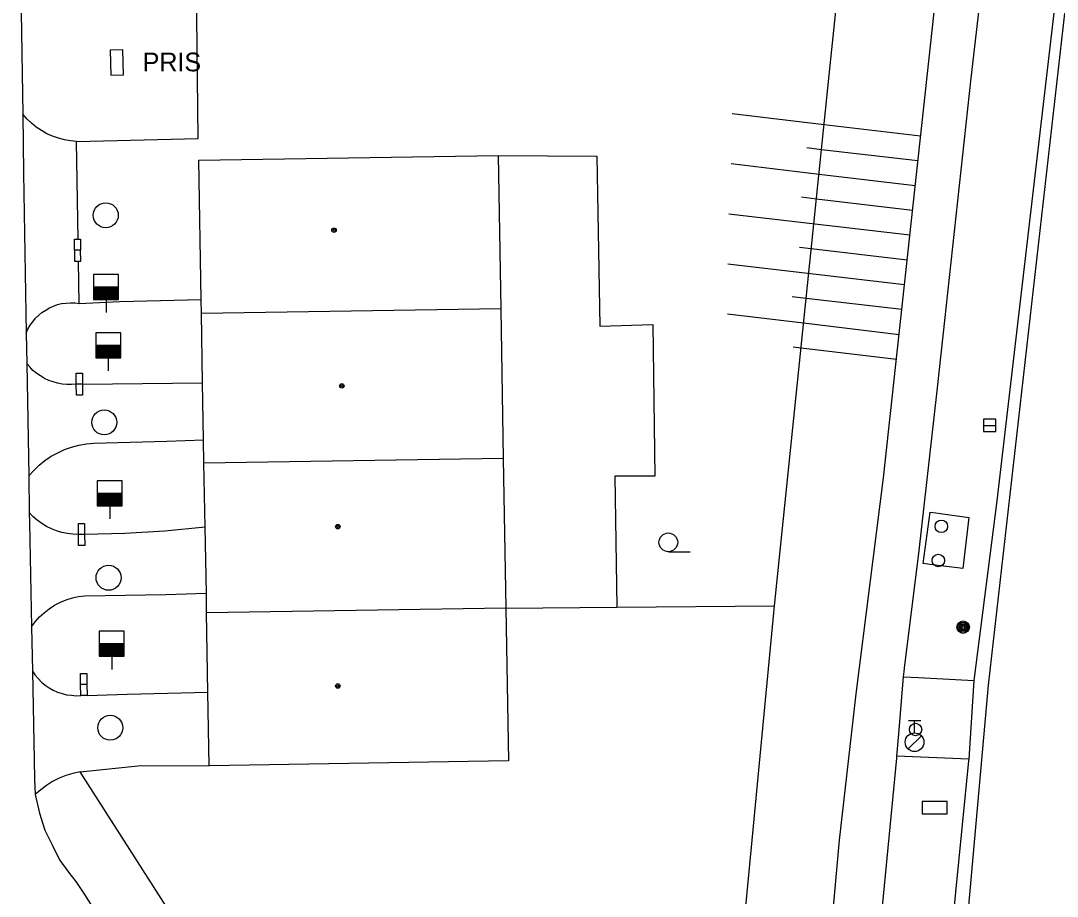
# Model space of a CAD drawing. Extents: x -595546 to -593986, y -1160845 to -1159202.
# Drawn here: x -594714.12 to -594672.57, y -1160187.36 to -1160152.26 of the extents above; entities that cross this region are included whole.
import ezdxf

# ---------------------------------------------------------------- set-up
doc = ezdxf.new("R2010")
doc.units = 0
for name, color, linetype in [('Level 24', 7, 'Continuous'), ('Level 25', 7, 'Continuous'), ('Level 27', 7, 'Continuous'), ('Level 28', 7, 'Continuous'), ('Level 36', 7, 'Continuous'), ('Level 39', 7, 'Continuous'), ('plynovod - povrch.  znaky - PRIS skut. velikost', 7, 'Continuous'), ('silnoproud - povrch.  znaky a  RIS  skut. velikost', 7, 'Continuous'), ('Specificka linie pasportu komunikaci', 7, 'Continuous'), ('TM - budovy zdene_ betonove - VP', 7, 'Continuous'), ('TM - chodniky - VP', 7, 'Continuous'), ('TM - komunikace - VP', 7, 'Continuous'), ('TM - letecke snimky - pomocna linie', 7, 'Continuous'), ('TM - popis objektu', 7, 'Continuous'), ('TM - rozhrani ploch obecne - VP', 7, 'Continuous'), ('TM - srafovani', 7, 'Continuous')]:
    doc.layers.add(name, color=color, linetype=linetype)

msp = doc.modelspace()

# ---------------------------------------------------------------- linework, layer by layer
at = {"layer": 'Level 24'}
for points in [[(-594710.533, -1160153.447), (-594710.507, -1160154.446), (-594710.007, -1160154.433), (-594710.033, -1160153.434)], [(-594677.987, -1160184.058), (-594676.987, -1160184.058), (-594676.987, -1160183.558), (-594677.987, -1160183.558)]]:
    msp.add_lwpolyline(points, close=True, dxfattribs=at)
at = {"layer": 'Level 25'}
for radius in [0.25, 0.2, 0.15, 0.1, 0.05]:
    msp.add_circle((-594676.34, -1160176.57), radius, dxfattribs=at)
at = {"layer": 'Level 27'}
msp.add_line((-594675.53, -1160168.48), (-594675.03, -1160168.48), dxfattribs=at)
msp.add_lwpolyline([(-594675.53, -1160168.73), (-594675.03, -1160168.73), (-594675.03, -1160168.23), (-594675.53, -1160168.23)], close=True, dxfattribs=at)
for centre in [(-594710.71, -1160160.06), (-594710.77, -1160168.36), (-594710.6, -1160174.59), (-594710.53, -1160180.6)]:
    msp.add_circle(centre, 0.5, dxfattribs=at)
at = {"layer": 'Level 28'}
for p, q in [((-594711.2, -1160162.93), (-594710.2, -1160162.93)), ((-594711.2, -1160162.98), (-594710.2, -1160162.98)), ((-594711.2, -1160163.03), (-594710.2, -1160163.03)), ((-594711.2, -1160163.08), (-594710.2, -1160163.08)), ((-594711.2, -1160163.13), (-594710.2, -1160163.13)), ((-594711.2, -1160163.18), (-594710.2, -1160163.18)), ((-594711.2, -1160163.23), (-594710.2, -1160163.23)), ((-594711.2, -1160163.28), (-594710.2, -1160163.28)), ((-594711.2, -1160163.33), (-594710.2, -1160163.33)), ((-594711.2, -1160163.38), (-594710.2, -1160163.38)), ((-594710.7, -1160163.43), (-594710.7, -1160163.96)), ((-594711.11, -1160165.27), (-594710.11, -1160165.27)), ((-594711.11, -1160165.32), (-594710.11, -1160165.32)), ((-594711.11, -1160165.37), (-594710.11, -1160165.37)), ((-594711.11, -1160165.42), (-594710.11, -1160165.42)), ((-594711.11, -1160165.47), (-594710.11, -1160165.47)), ((-594711.11, -1160165.52), (-594710.11, -1160165.52)), ((-594711.11, -1160165.57), (-594710.11, -1160165.57)), ((-594711.11, -1160165.62), (-594710.11, -1160165.62)), ((-594711.11, -1160165.67), (-594710.11, -1160165.67)), ((-594711.11, -1160165.72), (-594710.11, -1160165.72)), ((-594710.61, -1160165.77), (-594710.61, -1160166.3)), ((-594711.05, -1160171.2), (-594710.05, -1160171.2)), ((-594711.05, -1160171.25), (-594710.05, -1160171.25)), ((-594711.05, -1160171.3), (-594710.05, -1160171.3)), ((-594711.05, -1160171.35), (-594710.05, -1160171.35)), ((-594711.05, -1160171.4), (-594710.05, -1160171.4)), ((-594711.05, -1160171.45), (-594710.05, -1160171.45)), ((-594711.05, -1160171.5), (-594710.05, -1160171.5)), ((-594711.05, -1160171.55), (-594710.05, -1160171.55)), ((-594711.05, -1160171.6), (-594710.05, -1160171.6)), ((-594711.05, -1160171.65), (-594710.05, -1160171.65)), ((-594710.55, -1160171.7), (-594710.55, -1160172.23)), ((-594710.97, -1160177.23), (-594709.97, -1160177.23)), ((-594710.97, -1160177.28), (-594709.97, -1160177.28)), ((-594710.97, -1160177.33), (-594709.97, -1160177.33)), ((-594710.97, -1160177.38), (-594709.97, -1160177.38)), ((-594710.97, -1160177.43), (-594709.97, -1160177.43)), ((-594710.97, -1160177.48), (-594709.97, -1160177.48)), ((-594710.97, -1160177.53), (-594709.97, -1160177.53)), ((-594710.97, -1160177.58), (-594709.97, -1160177.58)), ((-594710.97, -1160177.63), (-594709.97, -1160177.63)), ((-594710.97, -1160177.68), (-594709.97, -1160177.68)), ((-594710.47, -1160177.73), (-594710.47, -1160178.26)), ((-594678.54, -1160180.305), (-594678.04, -1160180.305)), ((-594678.29, -1160180.805), (-594678.29, -1160180.305)), ((-594678.548, -1160181.452), (-594678.018, -1160180.922))]:
    msp.add_line(p, q, dxfattribs=at)
for points in [[(-594711.2, -1160163.43), (-594710.2, -1160163.43), (-594710.2, -1160162.43), (-594711.2, -1160162.43)], [(-594711.11, -1160165.77), (-594710.11, -1160165.77), (-594710.11, -1160164.77), (-594711.11, -1160164.77)], [(-594711.05, -1160171.7), (-594710.05, -1160171.7), (-594710.05, -1160170.7), (-594711.05, -1160170.7)], [(-594710.97, -1160177.73), (-594709.97, -1160177.73), (-594709.97, -1160176.73), (-594710.97, -1160176.73)]]:
    msp.add_lwpolyline(points, close=True, dxfattribs=at)
for centre, radius in [((-594677.22, -1160172.53), 0.25), ((-594677.34, -1160173.9), 0.25), ((-594678.25, -1160180.67), 0.25), ((-594678.29, -1160181.18), 0.375)]:
    msp.add_circle(centre, radius, dxfattribs=at)
at = {"layer": 'Level 36'}
msp.add_line((-594688.16, -1160173.545), (-594687.285, -1160173.545), dxfattribs=at)
msp.add_circle((-594688.16, -1160173.17), 0.375, dxfattribs=at)
at = {"layer": 'Level 39'}
for centre, radius in [((-594701.56, -1160160.66), 0.09), ((-594701.56, -1160160.66), 0.0398), ((-594701.25, -1160166.9), 0.09), ((-594701.25, -1160166.9), 0.0398), ((-594701.41, -1160172.54), 0.09), ((-594701.41, -1160172.54), 0.0398), ((-594701.41, -1160178.93), 0.09), ((-594701.41, -1160178.93), 0.0398)]:
    msp.add_circle(centre, radius, dxfattribs=at)
at = {"layer": 'plynovod - povrch.  znaky - PRIS skut. velikost'}
for points in [[(-594711.97, -1160161.02), (-594711.82, -1160161.02)], [(-594711.97, -1160161.46), (-594711.97, -1160161.02)], [(-594711.82, -1160161.02), (-594711.72, -1160161.02), (-594711.72, -1160161.46)], [(-594711.72, -1160161.46), (-594711.81, -1160161.46), (-594711.97, -1160161.46)], [(-594711.9, -1160166.39), (-594711.65, -1160166.39), (-594711.65, -1160166.83)], [(-594711.9, -1160166.83), (-594711.9, -1160166.39)], [(-594711.65, -1160166.83), (-594711.9, -1160166.83)], [(-594711.81, -1160172.41), (-594711.56, -1160172.41), (-594711.56, -1160172.85)], [(-594711.81, -1160172.85), (-594711.81, -1160172.41)], [(-594711.56, -1160172.85), (-594711.81, -1160172.85)], [(-594711.72, -1160178.87), (-594711.72, -1160178.43), (-594711.47, -1160178.43), (-594711.47, -1160178.87)], [(-594711.47, -1160178.87), (-594711.72, -1160178.87)]]:
    msp.add_lwpolyline(points, dxfattribs=at)
at = {"layer": 'silnoproud - povrch.  znaky a  RIS  skut. velikost'}
for points in [[(-594711.97, -1160161.46), (-594711.96, -1160161.9), (-594711.8, -1160161.9)], [(-594711.8, -1160161.9), (-594711.71, -1160161.9), (-594711.72, -1160161.46)], [(-594711.65, -1160166.83), (-594711.64, -1160167.27), (-594711.89, -1160167.27), (-594711.9, -1160166.83)], [(-594711.56, -1160172.85), (-594711.55, -1160173.29), (-594711.8, -1160173.29), (-594711.81, -1160172.85)], [(-594711.71, -1160179.31), (-594711.72, -1160178.87)], [(-594711.47, -1160178.87), (-594711.46, -1160179.31)], [(-594711.46, -1160179.31), (-594711.71, -1160179.31)]]:
    msp.add_lwpolyline(points, dxfattribs=at)
at = {"layer": 'Specificka linie pasportu komunikaci'}
for points in [[(-594670.43, -1160132.17), (-594672.44, -1160149.65), (-594674.99, -1160171.51), (-594675.92, -1160178.71)], [(-594678.73, -1160178.56), (-594678.13, -1160178.59), (-594675.92, -1160178.71)], [(-594675.92, -1160178.71), (-594676.12, -1160181.86)], [(-594676.12, -1160181.86), (-594679, -1160181.74)], [(-594676.12, -1160181.86), (-594676.13, -1160181.93), (-594677.42, -1160195.02), (-594677.85, -1160199.94)]]:
    msp.add_lwpolyline(points, dxfattribs=at)
at = {"layer": 'TM - budovy zdene_ betonove - VP'}
for points in [[(-594706.98, -1160157.85), (-594694.98, -1160157.66)], [(-594706.89, -1160163.43), (-594706.98, -1160157.85)], [(-594694.98, -1160157.66), (-594694.88, -1160163.81)], [(-594706.88, -1160164), (-594706.89, -1160163.43)], [(-594694.88, -1160163.81), (-594706.88, -1160164)], [(-594706.83, -1160166.77), (-594706.88, -1160164)], [(-594694.88, -1160163.81), (-594694.78, -1160169.81)], [(-594706.8, -1160169.06), (-594706.83, -1160166.77)], [(-594706.78, -1160170), (-594706.8, -1160169.06)], [(-594694.78, -1160169.81), (-594706.78, -1160170)], [(-594694.78, -1160169.81), (-594694.68, -1160175.81)], [(-594706.73, -1160172.56), (-594706.78, -1160170)], [(-594706.68, -1160175.2), (-594706.73, -1160172.56)], [(-594706.67, -1160175.99), (-594706.68, -1160175.2)], [(-594694.68, -1160175.81), (-594706.67, -1160175.99)], [(-594706.62, -1160179.17), (-594706.67, -1160175.99)], [(-594694.68, -1160175.81), (-594694.57, -1160181.93)], [(-594706.57, -1160182.13), (-594706.62, -1160179.17)], [(-594694.57, -1160181.93), (-594706.57, -1160182.13)]]:
    msp.add_lwpolyline(points, dxfattribs=at)
at = {"layer": 'TM - chodniky - VP'}
msp.add_lwpolyline([(-594679.54, -1160170.59), (-594674.28, -1160122.31), (-594671.81, -1160100.61)], dxfattribs=at)
at = {"layer": 'TM - komunikace - VP'}
for points in [[(-594678.62, -1160214.43), (-594678.31, -1160212.31), (-594675.32, -1160178.89), (-594668.98, -1160123.03)], [(-594714.12, -1160151.09), (-594714.04, -1160156.01)], [(-594714.04, -1160156.01), (-594714.01, -1160158.37), (-594713.9, -1160164.78)], [(-594713.9, -1160164.78), (-594713.88, -1160166)], [(-594713.88, -1160166), (-594713.8, -1160170.51)], [(-594713.8, -1160170.51), (-594713.78, -1160171.97)], [(-594713.78, -1160171.97), (-594713.77, -1160172.39), (-594713.69, -1160176.56)], [(-594713.69, -1160176.56), (-594713.65, -1160178.33)], [(-594713.65, -1160178.33), (-594713.58, -1160181.89)], [(-594713.58, -1160181.89), (-594713.57, -1160182.67), (-594713.54, -1160183.28)], [(-594713.54, -1160183.28), (-594713.37, -1160184.02), (-594713.15, -1160184.71), (-594712.85, -1160185.32), (-594712.56, -1160185.89), (-594712.21, -1160186.39), (-594711.91, -1160186.77), (-594711.56, -1160187.29), (-594711.24, -1160187.79), (-594710.82, -1160188.53), (-594710.32, -1160189.41), (-594709.82, -1160190.53), (-594709.45, -1160191.33), (-594709.12, -1160192.33), (-594708.86, -1160193.11)]]:
    msp.add_lwpolyline(points, dxfattribs=at)
at = {"layer": 'TM - letecke snimky - pomocna linie'}
for points in [[(-594678.73, -1160178.56), (-594678.71, -1160178.34), (-594678.68, -1160178.09), (-594678.66, -1160177.89), (-594678.11, -1160173.5), (-594677.39, -1160167.1), (-594677.07, -1160164.16), (-594677.03, -1160163.78), (-594676.02, -1160154.56), (-594672.8, -1160126.78), (-594670.58, -1160107.66)], [(-594683.91, -1160175.72), (-594681.67, -1160154.05), (-594679.43, -1160132.58)], [(-594711.88, -1160157.1), (-594707.01, -1160156.98), (-594707.07, -1160150.89)], [(-594711.88, -1160157.1), (-594712.13, -1160157.08), (-594712.37, -1160157.04), (-594712.61, -1160156.97), (-594712.85, -1160156.89), (-594713.08, -1160156.79), (-594713.29, -1160156.66), (-594713.5, -1160156.53), (-594713.69, -1160156.37), (-594713.87, -1160156.2), (-594714.04, -1160156.01)], [(-594711.82, -1160161.02), (-594711.88, -1160157.1)], [(-594694.98, -1160157.66), (-594691.03, -1160157.69), (-594690.9, -1160164.5), (-594688.78, -1160164.44), (-594688.7, -1160170.52), (-594690.3, -1160170.52), (-594690.23, -1160175.77)], [(-594711.78, -1160163.59), (-594711.8, -1160161.9)], [(-594713.9, -1160164.78), (-594713.83, -1160164.62), (-594713.74, -1160164.47), (-594713.64, -1160164.33), (-594713.53, -1160164.19), (-594713.4, -1160164.07), (-594713.27, -1160163.96), (-594713.12, -1160163.86), (-594712.97, -1160163.77), (-594712.81, -1160163.7), (-594712.65, -1160163.64), (-594712.48, -1160163.6), (-594712.3, -1160163.58), (-594712.13, -1160163.57), (-594711.95, -1160163.57), (-594711.78, -1160163.59)], [(-594711.78, -1160163.59), (-594710.15, -1160163.52), (-594708.52, -1160163.47), (-594706.89, -1160163.43)], [(-594711.9, -1160166.83), (-594712.09, -1160166.84), (-594712.27, -1160166.84), (-594712.46, -1160166.83), (-594712.64, -1160166.79), (-594712.82, -1160166.74), (-594713, -1160166.68), (-594713.17, -1160166.6), (-594713.33, -1160166.5), (-594713.48, -1160166.4), (-594713.63, -1160166.28), (-594713.76, -1160166.14), (-594713.88, -1160166)], [(-594711.65, -1160166.83), (-594706.83, -1160166.77)], [(-594711.19, -1160169.19), (-594709.73, -1160169.15), (-594708.26, -1160169.11), (-594706.8, -1160169.06)], [(-594713.8, -1160170.51), (-594713.6, -1160170.29), (-594713.38, -1160170.08), (-594713.15, -1160169.89), (-594712.9, -1160169.72), (-594712.63, -1160169.58), (-594712.36, -1160169.45), (-594712.08, -1160169.35), (-594711.79, -1160169.27), (-594711.49, -1160169.22), (-594711.19, -1160169.19)], [(-594677.56, -1160272.87), (-594678.04, -1160270.32), (-594678.05, -1160270.24), (-594680.18, -1160258.89), (-594680.93, -1160251.3), (-594680.92, -1160251.39), (-594681.16, -1160248.98), (-594682.31, -1160235.14), (-594683.11, -1160225.55), (-594683, -1160211.27), (-594682.28, -1160196.59), (-594681.98, -1160192.83), (-594681.62, -1160188.69), (-594681.6, -1160188.53), (-594681.3, -1160185.11), (-594680.63, -1160179.24), (-594679.54, -1160170.59)], [(-594711.81, -1160172.85), (-594712.03, -1160172.84), (-594712.25, -1160172.82), (-594712.47, -1160172.77), (-594712.68, -1160172.71), (-594712.89, -1160172.63), (-594713.09, -1160172.53), (-594713.28, -1160172.41), (-594713.46, -1160172.28), (-594713.63, -1160172.13), (-594713.78, -1160171.97)], [(-594706.73, -1160172.56), (-594708.34, -1160172.72), (-594709.95, -1160172.81), (-594711.56, -1160172.85)], [(-594711.55, -1160175.31), (-594709.93, -1160175.29), (-594708.3, -1160175.26), (-594706.68, -1160175.2)], [(-594713.69, -1160176.56), (-594713.54, -1160176.36), (-594713.37, -1160176.16), (-594713.18, -1160175.99), (-594712.98, -1160175.83), (-594712.76, -1160175.69), (-594712.53, -1160175.57), (-594712.3, -1160175.48), (-594712.05, -1160175.4), (-594711.8, -1160175.34), (-594711.55, -1160175.31)], [(-594690.23, -1160175.77), (-594683.91, -1160175.72)], [(-594685.16, -1160188.89), (-594683.91, -1160175.72)], [(-594694.68, -1160175.81), (-594690.23, -1160175.77)], [(-594713.65, -1160178.33), (-594713.54, -1160178.49), (-594713.42, -1160178.63), (-594713.29, -1160178.77), (-594713.14, -1160178.89), (-594712.98, -1160179), (-594712.82, -1160179.09), (-594712.64, -1160179.17), (-594712.46, -1160179.23), (-594712.28, -1160179.28), (-594712.09, -1160179.3), (-594711.9, -1160179.32), (-594711.71, -1160179.31)], [(-594679, -1160181.74), (-594678.92, -1160180.85), (-594678.73, -1160178.56)], [(-594711.46, -1160179.31), (-594709.85, -1160179.25), (-594708.23, -1160179.21), (-594706.62, -1160179.17)], [(-594680.56, -1160199.45), (-594680.26, -1160195.74), (-594679.84, -1160190.54), (-594679.8, -1160190.12), (-594679, -1160181.82), (-594679, -1160181.74)], [(-594711.74, -1160182.37), (-594709.29, -1160182.12), (-594706.57, -1160182.13)], [(-594711.74, -1160182.37), (-594712.03, -1160182.43), (-594712.31, -1160182.52), (-594712.58, -1160182.62), (-594712.84, -1160182.76), (-594713.09, -1160182.91), (-594713.32, -1160183.09), (-594713.54, -1160183.28)], [(-594707.76, -1160188.6), (-594711.74, -1160182.37)]]:
    msp.add_lwpolyline(points, dxfattribs=at)
at = {"layer": 'TM - rozhrani ploch obecne - VP'}
for points in [[(-594677.66, -1160174.06), (-594677.95, -1160174.02), (-594677.66, -1160171.96), (-594677.44, -1160171.99)], [(-594677.44, -1160171.99), (-594676.11, -1160172.18)], [(-594676.11, -1160172.18), (-594676.36, -1160174.22)], [(-594676.36, -1160174.22), (-594677.66, -1160174.06)]]:
    msp.add_lwpolyline(points, dxfattribs=at)
at = {"layer": 'TM - srafovani'}
for points in [[(-594678.05, -1160156.89), (-594681.92, -1160156.43), (-594685.6, -1160156)], [(-594678.16, -1160157.88), (-594682.02, -1160157.43), (-594682.61, -1160157.36)], [(-594678.26, -1160158.88), (-594682.12, -1160158.42), (-594685.64, -1160158)], [(-594678.37, -1160159.87), (-594682.22, -1160159.41), (-594682.82, -1160159.34)], [(-594678.48, -1160160.86), (-594685.74, -1160160.01)], [(-594678.59, -1160161.86), (-594682.43, -1160161.41), (-594682.9, -1160161.35)], [(-594678.7, -1160162.85), (-594685.77, -1160162.02)], [(-594678.8, -1160163.84), (-594682.64, -1160163.4), (-594683.2, -1160163.33)], [(-594678.91, -1160164.85), (-594682.74, -1160164.39), (-594685.79, -1160164.03)], [(-594679.02, -1160165.84), (-594682.84, -1160165.39), (-594683.16, -1160165.35)]]:
    msp.add_lwpolyline(points, dxfattribs=at)

# ---------------------------------------------------------------- texts
at = {"layer": 'TM - popis objektu'}
msp.add_text('PRIS', height=0.75, dxfattribs=at).set_placement((-594709.23, -1160154.29))

doc.saveas('drawing.dxf')
